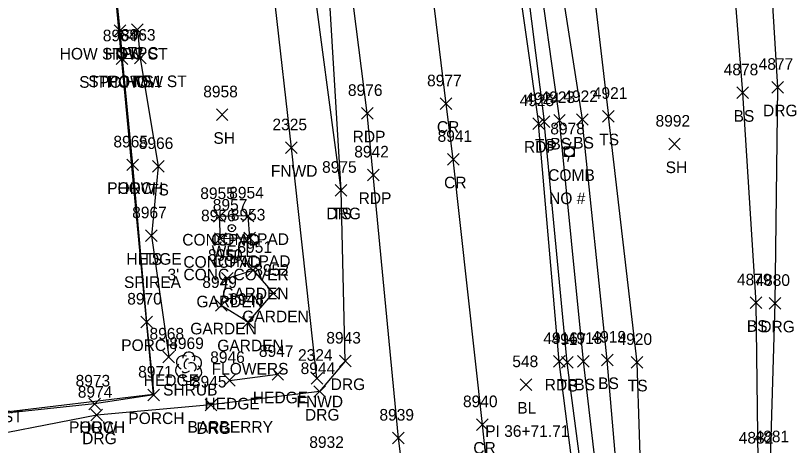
# Model space of a CAD drawing. Extents: x 1439173 to 1457902, y 641926 to 659889.
# Drawn here: x 1448240 to 1448374.4, y 646137 to 646210.9 of the extents above; entities that cross this region are included whole.
import ezdxf

# ---------------------------------------------------------------- set-up
doc = ezdxf.new("R2010")
doc.units = 0
for name, color, linetype in [('C_A', 7, 'Continuous'), ('C_C', 7, 'Continuous'), ('C_I', 7, 'Continuous'), ('C_TIC', 7, 'Continuous'), ('L_A', 7, 'Continuous'), ('L_C', 7, 'Continuous'), ('L_I', 7, 'Continuous'), ('L_TIC', 7, 'Continuous'), ('LAHR', 7, 'Continuous'), ('LAPB', 7, 'Continuous'), ('LBC', 7, 'Continuous'), ('LBF', 7, 'Continuous'), ('LELB', 7, 'Continuous'), ('Level 5', 7, 'Continuous'), ('LFNC', 7, 'Continuous'), ('LS', 7, 'Continuous'), ('LSH', 7, 'Continuous'), ('P_A', 7, 'Continuous'), ('P_I', 7, 'Continuous'), ('P_TIC', 7, 'Continuous'), ('PET', 7, 'Continuous'), ('PRC', 7, 'Continuous'), ('R_A', 7, 'Continuous'), ('R_I', 7, 'Continuous'), ('R_TIC', 7, 'Continuous'), ('RDG', 7, 'Continuous'), ('U_A', 7, 'Continuous'), ('U_C', 7, 'Continuous'), ('U_I', 7, 'Continuous'), ('UP', 7, 'Continuous'), ('UWW', 7, 'Continuous')]:
    doc.layers.add(name, color=color, linetype=linetype)

msp = doc.modelspace()

# ---------------------------------------------------------------- linework, layer by layer
at = {"layer": 'C_TIC'}
for points in [[(1448326.88, 646146.42), (1448328.88, 646148.42)], [(1448328.88, 646146.42), (1448326.88, 646148.42)]]:
    msp.add_lwpolyline(points, dxfattribs=at)
at = {"layer": 'L_TIC'}
for points in [[(1448256.99, 646207.38), (1448258.99, 646209.38)], [(1448258.99, 646207.38), (1448256.99, 646209.38)], [(1448256.99, 646207.38), (1448258.99, 646209.38)], [(1448258.99, 646207.38), (1448256.99, 646209.38)], [(1448259.99, 646207.52), (1448261.99, 646209.52)], [(1448261.99, 646207.52), (1448259.99, 646209.52)], [(1448260.47, 646202.63), (1448262.47, 646204.63)], [(1448262.47, 646202.63), (1448260.47, 646204.63)], [(1448260.47, 646202.63), (1448262.47, 646204.63)], [(1448262.47, 646202.63), (1448260.47, 646204.63)], [(1448257.34, 646202.52), (1448259.34, 646204.52)], [(1448259.34, 646202.52), (1448257.34, 646204.52)], [(1448257.34, 646202.52), (1448259.34, 646204.52)], [(1448259.34, 646202.52), (1448257.34, 646204.52)], [(1448364.14, 646196.67), (1448366.14, 646198.67)], [(1448366.14, 646196.67), (1448364.14, 646198.67)], [(1448274.58, 646192.87), (1448276.58, 646194.87)], [(1448276.58, 646192.87), (1448274.58, 646194.87)], [(1448332.63, 646191.89), (1448334.63, 646193.89)], [(1448334.63, 646191.89), (1448332.63, 646193.89)], [(1448336.55, 646192.06), (1448338.55, 646194.06)], [(1448338.55, 646192.06), (1448336.55, 646194.06)], [(1448341.05, 646192.61), (1448343.05, 646194.61)], [(1448343.05, 646192.61), (1448341.05, 646194.61)], [(1448329.99, 646191.7), (1448331.99, 646193.7)], [(1448331.99, 646191.7), (1448329.99, 646193.7)], [(1448286.49, 646187.2), (1448288.49, 646189.2)], [(1448288.49, 646187.2), (1448286.49, 646189.2)], [(1448352.42, 646187.83), (1448354.42, 646189.83)], [(1448354.42, 646187.83), (1448352.42, 646189.83)], [(1448259.17, 646184.25), (1448261.17, 646186.25)], [(1448261.17, 646184.25), (1448259.17, 646186.25)], [(1448259.17, 646184.25), (1448261.17, 646186.25)], [(1448261.17, 646184.25), (1448259.17, 646186.25)], [(1448263.58, 646183.98), (1448265.58, 646185.98)], [(1448265.58, 646183.98), (1448263.58, 646185.98)], [(1448295.03, 646179.88), (1448297.03, 646181.88)], [(1448297.03, 646179.88), (1448295.03, 646181.88)], [(1448274.07, 646175.36), (1448276.07, 646177.36)], [(1448276.07, 646175.36), (1448274.07, 646177.36)], [(1448279.05, 646175.46), (1448281.05, 646177.46)], [(1448281.05, 646175.46), (1448279.05, 646177.46)], [(1448262.4, 646172.05), (1448264.4, 646174.05)], [(1448264.4, 646172.05), (1448262.4, 646174.05)], [(1448262.4, 646172.05), (1448264.4, 646174.05)], [(1448264.4, 646172.05), (1448262.4, 646174.05)], [(1448274.26, 646171.53), (1448276.26, 646173.53)], [(1448276.26, 646171.53), (1448274.26, 646173.53)], [(1448274.26, 646171.53), (1448276.26, 646173.53)], [(1448276.26, 646171.53), (1448274.26, 646173.53)], [(1448279.32, 646171.67), (1448281.32, 646173.67)], [(1448281.32, 646171.67), (1448279.32, 646173.67)], [(1448279.32, 646171.67), (1448281.32, 646173.67)], [(1448281.32, 646171.67), (1448279.32, 646173.67)], [(1448279.9, 646166.1), (1448281.9, 646168.1)], [(1448281.9, 646166.1), (1448279.9, 646168.1)], [(1448275.48, 646164.72), (1448277.48, 646166.72)], [(1448277.48, 646164.72), (1448275.48, 646166.72)], [(1448283.37, 646162.15), (1448285.37, 646164.15)], [(1448285.37, 646162.15), (1448283.37, 646164.15)], [(1448283.37, 646162.15), (1448285.37, 646164.15)], [(1448285.37, 646162.15), (1448283.37, 646164.15)], [(1448274.42, 646160.06), (1448276.42, 646162.06)], [(1448276.42, 646160.06), (1448274.42, 646162.06)], [(1448366.43, 646160.5), (1448368.43, 646162.5)], [(1448368.43, 646160.5), (1448366.43, 646162.5)], [(1448261.58, 646157.2), (1448263.58, 646159.2)], [(1448263.58, 646157.2), (1448261.58, 646159.2)], [(1448279.06, 646157.15), (1448281.06, 646159.15)], [(1448281.06, 646157.15), (1448279.06, 646159.15)], [(1448279.06, 646157.15), (1448281.06, 646159.15)], [(1448281.06, 646157.15), (1448279.06, 646159.15)], [(1448265.38, 646151.18), (1448267.38, 646153.18)], [(1448267.38, 646151.18), (1448265.38, 646153.18)], [(1448333.96, 646150.24), (1448335.96, 646152.24)], [(1448335.96, 646150.24), (1448333.96, 646152.24)], [(1448336.74, 646150.43), (1448338.74, 646152.43)], [(1448338.74, 646150.43), (1448336.74, 646152.43)], [(1448340.84, 646150.65), (1448342.84, 646152.65)], [(1448342.84, 646150.65), (1448340.84, 646152.65)], [(1448345.97, 646150.25), (1448347.97, 646152.25)], [(1448347.97, 646150.25), (1448345.97, 646152.25)], [(1448284.16, 646148.19), (1448286.16, 646150.19)], [(1448286.16, 646148.19), (1448284.16, 646150.19)], [(1448275.84, 646147.14), (1448277.84, 646149.14)], [(1448277.84, 646147.14), (1448275.84, 646149.14)], [(1448290.89, 646147.51), (1448292.89, 646149.51)], [(1448292.89, 646147.51), (1448290.89, 646149.51)], [(1448262.81, 646144.63), (1448264.81, 646146.63)], [(1448264.81, 646144.63), (1448262.81, 646146.63)], [(1448252.61, 646143.09), (1448254.61, 646145.09)], [(1448254.61, 646143.09), (1448252.61, 646145.09)], [(1448252.61, 646143.09), (1448254.61, 646145.09)], [(1448254.61, 646143.09), (1448252.61, 646145.09)]]:
    msp.add_lwpolyline(points, dxfattribs=at)
at = {"layer": 'LAHR'}
for points in [[(1448263.4, 646173.05), (1448266.38, 646152.18)], [(1448276.84, 646148.14), (1448285.16, 646149.19)]]:
    msp.add_lwpolyline(points, dxfattribs=at)
at = {"layer": 'LAPB'}
for points in [[(1448280.06, 646158.15), (1448275.42, 646161.06), (1448276.48, 646165.72), (1448280.9, 646167.1), (1448284.37, 646163.15)], [(1448280.06, 646158.15), (1448284.37, 646163.15)]]:
    msp.add_lwpolyline(points, dxfattribs=at)
at = {"layer": 'LBC'}
for points in [[(1448256.47, 646222.71), (1448257.99, 646208.38), (1448258.34, 646203.52), (1448260.17, 646185.25)], [(1448253.61, 646144.09), (1448233.61, 646141.97), (1448233.04, 646145.93), (1448232.82, 646151.41), (1448230.95, 646166.11)]]:
    msp.add_lwpolyline(points, dxfattribs=at)
at = {"layer": 'LBF'}
for points in [[(1448257.99, 646208.38), (1448260.99, 646208.52), (1448261.47, 646203.63), (1448258.34, 646203.52)], [(1448260.17, 646185.25), (1448262.58, 646158.2), (1448263.81, 646145.63), (1448253.61, 646144.09)]]:
    msp.add_lwpolyline(points, dxfattribs=at)
at = {"layer": 'LELB'}
for points in [[(1448296.03, 646180.88), (1448290.72, 646221.1), (1448287.61, 646237.31), (1448286.97, 646249.77), (1448285.59, 646270.76), (1448281.89, 646306.51), (1448275.17, 646350.37), (1448271.57, 646377.15), (1448266.22, 646406.8), (1448259.66, 646452.28), (1448254.33, 646482.74), (1448250.69, 646509.1), (1448243.06, 646549.57), (1448238.14, 646585.37), (1448235.4, 646595.39), (1448223.99, 646612.78), (1448216.43, 646615.7)], [(1448338.62, 646223.04), (1448342.05, 646193.61)], [(1448327.34, 646221.84), (1448330.99, 646192.7)], [(1448329.57, 646222), (1448333.63, 646192.89)], [(1448333.1, 646221.41), (1448337.55, 646193.06)], [(1448363.28, 646221.01), (1448365.14, 646197.67)], [(1448261.47, 646203.63), (1448264.58, 646184.98), (1448263.4, 646173.05)], [(1448365.14, 646197.67), (1448367.43, 646161.5), (1448367.74, 646134.27), (1448364.61, 646120.06), (1448365.2, 646113.88), (1448365.78, 646100.64), (1448363.06, 646092.95), (1448358.07, 646085.32), (1448353.56, 646082.74)], [(1448353.56, 646082.74), (1448348.28, 646082.87), (1448344.35, 646084.39), (1448343.4, 646086.42), (1448341.49, 646091.34), (1448339.85, 646114.1), (1448334.96, 646151.24), (1448330.99, 646192.7)], [(1448345.29, 646085.44), (1448343.49, 646091.86), (1448342.11, 646114.05), (1448337.74, 646151.43), (1448333.63, 646192.89)], [(1448345.29, 646085.44), (1448346.86, 646085.45), (1448346.93, 646092.26), (1448341.84, 646151.65), (1448337.55, 646193.06)], [(1448353.56, 646082.74), (1448353.3, 646093.37), (1448351.83, 646114.05), (1448348.18, 646114.06), (1448346.97, 646151.25), (1448342.05, 646193.61)]]:
    msp.add_lwpolyline(points, dxfattribs=at)
at = {"layer": 'Level 5'}
for p, q in [((1448256.38, 646222.6), (1448263.7, 646145.72)), ((1448263.7, 646145.72), (1448233.98, 646142.16))]:
    msp.add_line(p, q, dxfattribs=at)
at = {"layer": 'LFNC'}
msp.add_lwpolyline([(1448291.89, 646148.51), (1448287.49, 646188.2), (1448281.86, 646237.8)], dxfattribs=at)
at = {"layer": 'LS'}
for points in [[(1448280.32, 646172.67), (1448280.05, 646176.46), (1448275.07, 646176.36), (1448275.26, 646172.53)], [(1448280.32, 646172.67), (1448275.26, 646172.53)]]:
    msp.add_lwpolyline(points, dxfattribs=at)
at = {"layer": 'LSH'}
msp.add_line((1448269.78, 646150.54), (1448269.78, 646150.54), dxfattribs=at)
msp.add_line((1448269.78, 646150.54), (1448269.78, 646150.54), dxfattribs=at)
msp.add_arc((1448269.83, 646151.97), 1.05, 335.5272, 180.9563, dxfattribs=at)
for centre, major_axis, ratio, start_param, end_param in [((1448268.99, 646151.21), (1.21, -0.51), 0.895232, 1.570796, 4.712389), ((1448270.82, 646151.12), (-1.14, -0.48), 0.949671, 1.570796, 4.712389), ((1448269.57, 646151), (-0.208, -0.792), 0.645439, 3.141593, 6.283185), ((1448270.28, 646150.37), (-0.5, 0.667), 0.989748, 3.141593, 6.283185), ((1448268.7, 646149.83), (0.58, -1.04), 0.959034, 3.141593, 6.283185), ((1448269.32, 646149.79), (-0.625, -0.083), 0.423636, 0, 3.141593), ((1448270.78, 646149.71), (-1.09, 0.79), 0.841452, 1.570796, 4.712389), ((1448269.78, 646149.04), (0.26, 1.06), 0.942809, 1.570796, 4.712389)]:
    msp.add_ellipse(centre, major_axis=major_axis, ratio=ratio, start_param=start_param, end_param=end_param, dxfattribs=at)
at = {"layer": 'P_TIC'}
for points in [[(1448313.1, 646194.77), (1448315.1, 646196.77)], [(1448315.1, 646194.77), (1448313.1, 646196.77)], [(1448299.54, 646193.12), (1448301.54, 646195.12)], [(1448301.54, 646193.12), (1448299.54, 646195.12)], [(1448329.03, 646191.36), (1448331.03, 646193.36)], [(1448331.03, 646191.36), (1448329.03, 646193.36)], [(1448314.34, 646185.21), (1448316.34, 646187.21)], [(1448316.34, 646185.21), (1448314.34, 646187.21)], [(1448300.57, 646182.52), (1448302.57, 646184.52)], [(1448302.57, 646182.52), (1448300.57, 646184.52)], [(1448332.6, 646150.41), (1448334.6, 646152.41)], [(1448334.6, 646150.41), (1448332.6, 646152.41)], [(1448319.37, 646139.53), (1448321.37, 646141.53)], [(1448321.37, 646139.53), (1448319.37, 646141.53)], [(1448304.91, 646137.22), (1448306.91, 646139.22)], [(1448306.91, 646137.22), (1448304.91, 646139.22)]]:
    msp.add_lwpolyline(points, dxfattribs=at)
at = {"layer": 'PET'}
for points in [[(1448331.09, 645886.39), (1448326.63, 645936.53), (1448323.37, 645969.74), (1448318.61, 646019.75), (1448314.85, 646060.49), (1448310.56, 646101.37), (1448305.91, 646138.22), (1448301.57, 646183.52), (1448300.54, 646194.12), (1448294.77, 646239.41), (1448289.46, 646272.11), (1448284.57, 646306.83), (1448278.36, 646350.9), (1448273.98, 646377.73), (1448269.75, 646406.45), (1448262.13, 646452.79), (1448257.52, 646483.03), (1448252.72, 646509.61), (1448246.46, 646550.34), (1448240.19, 646586.21)], [(1448325.91, 646221.48), (1448330.03, 646192.36)], [(1448352.01, 645968.3), (1448347.84, 646009.58), (1448344.31, 646045.25), (1448340.76, 646084.28), (1448338.34, 646114.03), (1448333.6, 646151.41), (1448330.03, 646192.36)]]:
    msp.add_lwpolyline(points, dxfattribs=at)
at = {"layer": 'PRC'}
msp.add_lwpolyline([(1448345.39, 645887.63), (1448340.89, 645937.21), (1448337.6, 645971.85), (1448332.94, 646019.26), (1448328.46, 646064), (1448324.3, 646103.05), (1448320.37, 646140.53), (1448315.34, 646186.21), (1448314.1, 646195.77), (1448308.6, 646240.95), (1448301.99, 646288.45), (1448298.89, 646310.52), (1448292.09, 646353.02), (1448288.02, 646380.98), (1448283.91, 646408.77), (1448276.49, 646455.17), (1448271.43, 646484.75), (1448267.22, 646512.05), (1448260.65, 646552.87), (1448253.95, 646593.27)], dxfattribs=at)
at = {"layer": 'R_TIC'}
for points in [[(1448370.17, 646197.61), (1448372.17, 646199.61)], [(1448372.17, 646197.61), (1448370.17, 646199.61)], [(1448295.03, 646179.88), (1448297.03, 646181.88)], [(1448297.03, 646179.88), (1448295.03, 646181.88)], [(1448369.7, 646160.41), (1448371.7, 646162.41)], [(1448371.7, 646160.41), (1448369.7, 646162.41)], [(1448295.76, 646150.48), (1448297.76, 646152.48)], [(1448297.76, 646150.48), (1448295.76, 646152.48)], [(1448295.76, 646150.48), (1448297.76, 646152.48)], [(1448297.76, 646150.48), (1448295.76, 646152.48)], [(1448291.34, 646145.23), (1448293.34, 646147.23)], [(1448293.34, 646145.23), (1448291.34, 646147.23)], [(1448272.63, 646142.92), (1448274.63, 646144.92)], [(1448274.63, 646142.92), (1448272.63, 646144.92)], [(1448252.99, 646141.16), (1448254.99, 646143.16)], [(1448254.99, 646141.16), (1448252.99, 646143.16)]]:
    msp.add_lwpolyline(points, dxfattribs=at)
at = {"layer": 'RDG'}
for points in [[(1448296.76, 646151.48), (1448296.03, 646180.88), (1448293.65, 646220.82), (1448288.75, 646250.12), (1448289.46, 646272.11)], [(1448369.69, 646222.13), (1448371.17, 646198.61)], [(1448371.17, 646198.61), (1448370.7, 646161.41), (1448369.9, 646134.49), (1448369.48, 646117.26), (1448368.13, 646100.54), (1448368.09, 646091.02), (1448362.14, 646083.27), (1448352.21, 646077.94)], [(1448296.76, 646151.48), (1448292.34, 646146.23), (1448273.63, 646143.92), (1448253.99, 646142.16), (1448229.77, 646137.47), (1448226.47, 646136.99), (1448207.59, 646135.28), (1448176.92, 646130.75)]]:
    msp.add_lwpolyline(points, dxfattribs=at)
at = {"layer": 'UP'}
for p, q in [((1448335.56, 646189.16), (1448335.31, 646188.33)), ((1448334.48, 646186.66), (1448334.48, 646188.33)), ((1448334.48, 646188.33), (1448336.14, 646188.33)), ((1448335.31, 646187.49), (1448335.31, 646187.49)), ((1448336.14, 646188.33), (1448336.14, 646186.66)), ((1448336.14, 646186.66), (1448334.48, 646186.66)), ((1448335.06, 646185.83), (1448335.31, 646186.66))]:
    msp.add_line(p, q, dxfattribs=at)
msp.add_circle((1448335.31, 646187.49), 0.833, dxfattribs=at)
at = {"layer": 'UWW'}
for radius in [0.625, 0.0833]:
    msp.add_circle((1448277.22, 646174.37), radius, dxfattribs=at)

# ---------------------------------------------------------------- texts
at = {"layer": 'C_A'}
msp.add_text('BL', height=2, dxfattribs=at).set_placement((1448326.36, 646142.42))
at = {"layer": 'C_C'}
msp.add_text('PI 36+71.71', height=2, dxfattribs=at).set_placement((1448320.84, 646138.42))
at = {"layer": 'C_I'}
msp.add_text('548', height=2, dxfattribs=at).set_placement((1448325.51, 646150.42))
at = {"layer": 'L_A'}
for s, p in [('HOW STPC ST', (1448247.62, 646203.38)), ('HOW', (1448255.38, 646203.38)), ('STPC', (1448257.5, 646203.52)), ('STPC TS1 ST', (1448252.53, 646198.63)), ('TS', (1448259.88, 646198.63)), ('STPC HOW', (1448250.97, 646198.52)), ('HOW', (1448255.72, 646198.52)), ('BS', (1448363.59, 646192.67)), ('SH', (1448274.07, 646188.87)), ('BS', (1448332.07, 646187.89)), ('BS', (1448335.99, 646188.06)), ('TS', (1448340.46, 646188.61)), ('TS', (1448329.4, 646187.7)), ('SH', (1448351.9, 646183.83)), ('FNWD', (1448283.95, 646183.2)), ('PORCH', (1448255.79, 646180.25)), ('HOW', (1448257.55, 646180.25)), ('TS', (1448262.99, 646179.98)), ('TS', (1448294.44, 646175.88)), ('CONCPAD', (1448268.71, 646171.36)), ('CONCPAD', (1448273.7, 646171.46)), ('HEDGE', (1448259.1, 646168.05)), ('TS', (1448261.81, 646168.05)), ('CONCPAD', (1448273.96, 646167.67)), ('CONCPAD', (1448273.96, 646167.67)), ('CONCPAD', (1448268.9, 646167.53)), ('CONCPAD', (1448268.9, 646167.53)), ('GARDEN', (1448275.57, 646162.1)), ('GARDEN', (1448271.15, 646160.72)), ('GARDEN', (1448279.04, 646158.15)), ('GARDEN', (1448279.04, 646158.15)), ('GARDEN', (1448270.09, 646156.06)), ('BS', (1448365.87, 646156.5)), ('PORCH', (1448258.2, 646153.2)), ('GARDEN', (1448274.73, 646153.15)), ('GARDEN', (1448274.73, 646153.15)), ('HEDGE', (1448262.08, 646147.18)), ('TS', (1448333.37, 646146.24)), ('BS', (1448336.18, 646146.43)), ('BS', (1448340.28, 646146.65)), ('TS', (1448345.38, 646146.25)), ('SHRUB', (1448265.41, 646145.54)), ('HEDGE', (1448280.86, 646144.19)), ('FNWD', (1448288.36, 646143.51)), ('HEDGE', (1448272.54, 646143.14)), ('HOW STPC ST', (1448222.67, 646140.93)), ('PORCH', (1448259.43, 646140.63)), ('PORCH', (1448249.23, 646139.09)), ('HOW', (1448251, 646139.09))]:
    msp.add_text(s, height=2, dxfattribs=at).set_placement(p)
at = {"layer": 'L_C'}
for s, p in [('SPIREA', (1448258.68, 646164.05)), ('FLOWERS', (1448273.76, 646149.15)), ('FLOWERS', (1448273.76, 646149.15)), ('BARBERRY', (1448269.61, 646139.14))]:
    msp.add_text(s, height=2, dxfattribs=at).set_placement(p)
at = {"layer": 'L_I'}
for s, p in [('8963', (1448258.16, 646206.63)), ('8963', (1448258.16, 646206.63)), ('8964', (1448255.03, 646206.52)), ('8964', (1448255.03, 646206.52)), ('4878', (1448361.89, 646200.67)), ('8958', (1448272.32, 646196.87)), ('4923', (1448330.37, 646195.89)), ('4922', (1448334.29, 646196.06)), ('4921', (1448339.36, 646196.61)), ('4924', (1448327.73, 646195.7)), ('2325', (1448284.23, 646191.2)), ('8992', (1448350.16, 646191.83)), ('8965', (1448256.86, 646188.25)), ('8965', (1448256.86, 646188.25)), ('8966', (1448261.22, 646187.98)), ('8975', (1448292.77, 646183.88)), ('8955', (1448271.81, 646179.36)), ('8954', (1448276.79, 646179.46)), ('8967', (1448260.09, 646176.05)), ('8967', (1448260.09, 646176.05)), ('8956', (1448271.94, 646175.53)), ('8956', (1448271.94, 646175.53)), ('8953', (1448277.06, 646175.67)), ('8953', (1448277.06, 646175.67)), ('8951', (1448278.2, 646170.1)), ('8950', (1448273.13, 646168.72)), ('8952', (1448281.11, 646166.15)), ('8952', (1448281.11, 646166.15)), ('8949', (1448272.16, 646164.06)), ('4879', (1448364.17, 646164.5)), ('8970', (1448259.24, 646161.2)), ('8948', (1448276.8, 646161.15)), ('8948', (1448276.8, 646161.15)), ('8968', (1448263.07, 646155.18)), ('4917', (1448332.26, 646154.24)), ('4918', (1448335.05, 646154.43)), ('4919', (1448339.14, 646154.65)), ('4920', (1448343.62, 646154.25)), ('8969', (1448266.47, 646153.54)), ('8947', (1448281.9, 646152.19)), ('8946', (1448273.52, 646151.14)), ('2324', (1448288.63, 646151.51)), ('8971', (1448261.11, 646148.63)), ('8973', (1448250.35, 646147.09)), ('8973', (1448250.35, 646147.09)), ('4882', (1448364.48, 646137.27))]:
    msp.add_text(s, height=2, dxfattribs=at).set_placement(p)
at = {"layer": 'P_A'}
for s, p in [('CR', (1448312.53, 646190.77)), ('RDP', (1448298.03, 646189.12)), ('RDP', (1448327.52, 646187.36)), ('CR', (1448313.77, 646181.21)), ('RDP', (1448299.06, 646178.52)), ('RDP', (1448331.09, 646146.41)), ('CR', (1448318.8, 646135.53))]:
    msp.add_text(s, height=2, dxfattribs=at).set_placement(p)
at = {"layer": 'P_I'}
for s, p in [('8977', (1448310.84, 646198.77)), ('8976', (1448297.22, 646197.12)), ('4925', (1448326.77, 646195.36)), ('8941', (1448312.65, 646189.21)), ('8942', (1448298.31, 646186.52)), ('4916', (1448330.85, 646154.41)), ('8940', (1448317.02, 646143.53)), ('8939', (1448302.64, 646141.22))]:
    msp.add_text(s, height=2, dxfattribs=at).set_placement(p)
at = {"layer": 'R_A'}
for p in [(1448368.66, 646193.61), (1448293.52, 646175.88), (1448368.19, 646156.41), (1448294.25, 646146.48), (1448294.25, 646146.48), (1448289.83, 646141.23), (1448271.12, 646138.92), (1448251.48, 646137.16)]:
    msp.add_text('DRG', height=2, dxfattribs=at).set_placement(p)
at = {"layer": 'R_I'}
for s, p in [('4877', (1448367.91, 646201.61)), ('8975', (1448292.77, 646183.88)), ('4880', (1448367.35, 646164.41)), ('8943', (1448293.5, 646154.48)), ('8943', (1448293.5, 646154.48)), ('8944', (1448289.08, 646149.23)), ('8945', (1448270.37, 646146.92)), ('8974', (1448250.73, 646145.16)), ('4881', (1448367.2, 646137.49)), ('8932', (1448290.57, 646136.52))]:
    msp.add_text(s, height=2, dxfattribs=at).set_placement(p)
at = {"layer": 'U_A'}
for s, p in [('COMB', (1448331.69, 646182.49)), ('WELL', (1448273.78, 646169.37))]:
    msp.add_text(s, height=2, dxfattribs=at).set_placement(p)
at = {"layer": 'U_C'}
for s, p in [('NO #', (1448331.84, 646178.49)), ("3' CONC COVER", (1448266.17, 646165.37))]:
    msp.add_text(s, height=2, dxfattribs=at).set_placement(p)
at = {"layer": 'U_I'}
for s, p in [('8978', (1448332.05, 646190.49)), ('8957', (1448273.96, 646177.37))]:
    msp.add_text(s, height=2, dxfattribs=at).set_placement(p)

doc.saveas('drawing.dxf')
